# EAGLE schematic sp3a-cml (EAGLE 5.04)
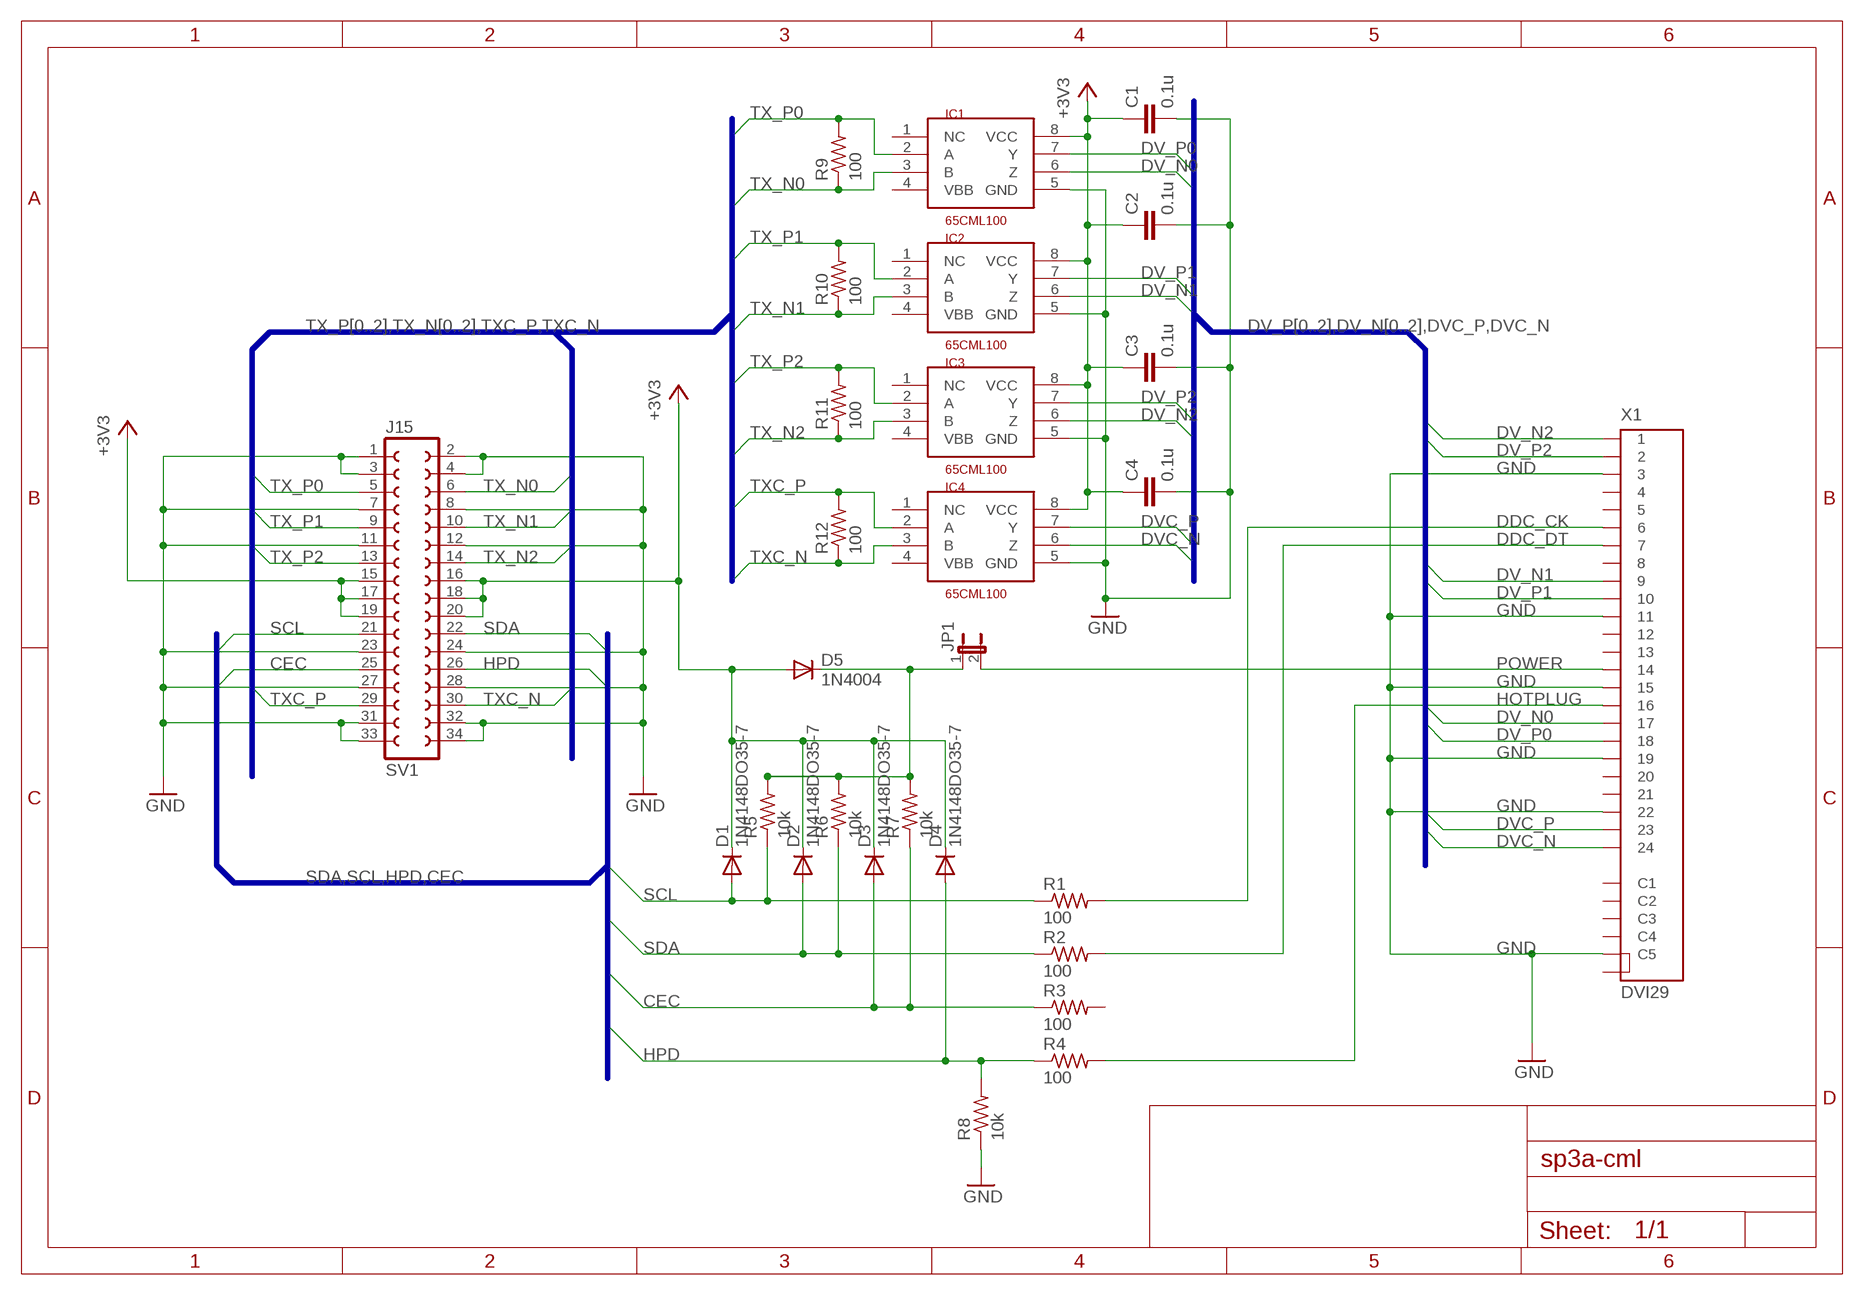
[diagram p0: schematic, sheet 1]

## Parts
C1  0.1u  C-EU050-025X075  [C050-025X075]
C2  0.1u  C-EU050-025X075  [C050-025X075]
C3  0.1u  C-EU050-025X075  [C050-025X075]
C4  0.1u  C-EU050-025X075  [C050-025X075]
D1  1N4148DO35-7  [DO35-7]
D2  1N4148DO35-7  [DO35-7]
D3  1N4148DO35-7  [DO35-7]
D4  1N4148DO35-7  [DO35-7]
D5  1N4004  [DO41-10]
IC1  65CML100  [SO-08]
IC2  65CML100  [SO-08]
IC3  65CML100  [SO-08]
IC4  65CML100  [SO-08]
JP1  JP1E  [JP1]
R1  100  R-US_0204/5  [0204/5]
R2  100  R-US_0204/5  [0204/5]
R3  100  R-US_0204/5  [0204/5]
R4  100  R-US_0204/5  [0204/5]
R5  10k  R-US_0204/5  [0204/5]
R6  10k  R-US_0204/5  [0204/5]
R7  10k  R-US_0204/5  [0204/5]
R8  10k  R-US_0204/5  [0204/5]
R9  100  R-US_0204/5  [0204/5]
R10  100  R-US_0204/5  [0204/5]
R11  100  R-US_0204/5  [0204/5]
R12  100  R-US_0204/5  [0204/5]
SV1  J15  FE17-2W  [FE17-2W]
X1  DVI29  [CCDVI-29DVISIR-A-2]

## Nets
+3V3: C1.1 C2.1 C3.1 C4.1 D1.C D2.C D3.C D4.C D5.A IC1.8(VCC) IC2.8(VCC) IC3.8(VCC) IC4.8(VCC) SV1.15 SV1.16 SV1.17 SV1.18 SV1.19 SV1.20
CEC: D3.A R3.1 R7.1 SV1.25
DDC_CK: R1.2 X1.6
DDC_DT: R2.2 X1.7
DV_N0: IC1.6(Z) X1.17
DV_N1: IC2.6(Z) X1.9
DV_N2: IC3.6(Z) X1.1
DV_P0: IC1.7(Y) X1.18
DV_P1: IC2.7(Y) X1.10
DV_P2: IC3.7(Y) X1.2
DVC_N: IC4.6(Z) X1.24
DVC_P: IC4.7(Y) X1.23
GND: C1.2 C2.2 C3.2 C4.2 IC1.5(GND) IC2.5(GND) IC3.5(GND) IC4.5(GND) R8.1 SV1.1 SV1.2 SV1.3 SV1.4 SV1.7 SV1.8 SV1.11 SV1.12 SV1.23 SV1.24 SV1.27 SV1.28 SV1.31 SV1.32 SV1.33 SV1.34 X1.3 X1.11 X1.15 X1.19 X1.22 X1.C5.1(C5)
HOTPLUG: R4.2 X1.16
HPD: D4.A R4.1 R8.2 SV1.26
N$3: D5.C JP1.1 R5.2 R6.2 R7.2
POWER: JP1.2 X1.14
SCL: D1.A R1.1 R5.1 SV1.21
SDA: D2.A R2.1 R6.1 SV1.22
TX_N0: IC1.3(B) R9.1 SV1.6
TX_N1: IC2.3(B) R10.1 SV1.10
TX_N2: IC3.3(B) R11.1 SV1.14
TX_P0: IC1.2(A) R9.2 SV1.5
TX_P1: IC2.2(A) R10.2 SV1.9
TX_P2: IC3.2(A) R11.2 SV1.13
TXC_N: IC4.3(B) R12.1 SV1.30
TXC_P: IC4.2(A) R12.2 SV1.29
Unconnected: IC1.1(NC) IC1.4(VBB) IC2.1(NC) IC2.4(VBB) IC3.1(NC) IC3.4(VBB) IC4.1(NC) IC4.4(VBB) R3.2 X1.4 X1.5 X1.8 X1.12 X1.13 X1.20 X1.21 X1.C1 X1.C2 X1.C3 X1.C4 X1.C5.2

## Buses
TX_P[0..2],TX_N[0..2],TXC_P,TXC_N
SDA,SCL,HPD,CEC
DV_P[0..2],DV_N[0..2],DVC_P,DVC_N

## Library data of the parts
C1-C4 = sheet1:C-EU: CAPACITOR, European symbol
D1-D4 = sheet1:1N4148: DIODE
D5 = sheet1:1N4004: DIODE
IC1-IC4 = sheet1:65CML100
JP1 = sheet1:JP1E: JUMPER
R1-R12 = sheet1:R-US_: RESISTOR, American symbol
SV1 = sheet1:FE17-2W: FEMALE HEADER
X1 = sheet1:DVI29: DVI 29 Connctor Source: http://www.cypressindustries.com/pdf/CCDVI-29DVISIR-A-2.pdf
